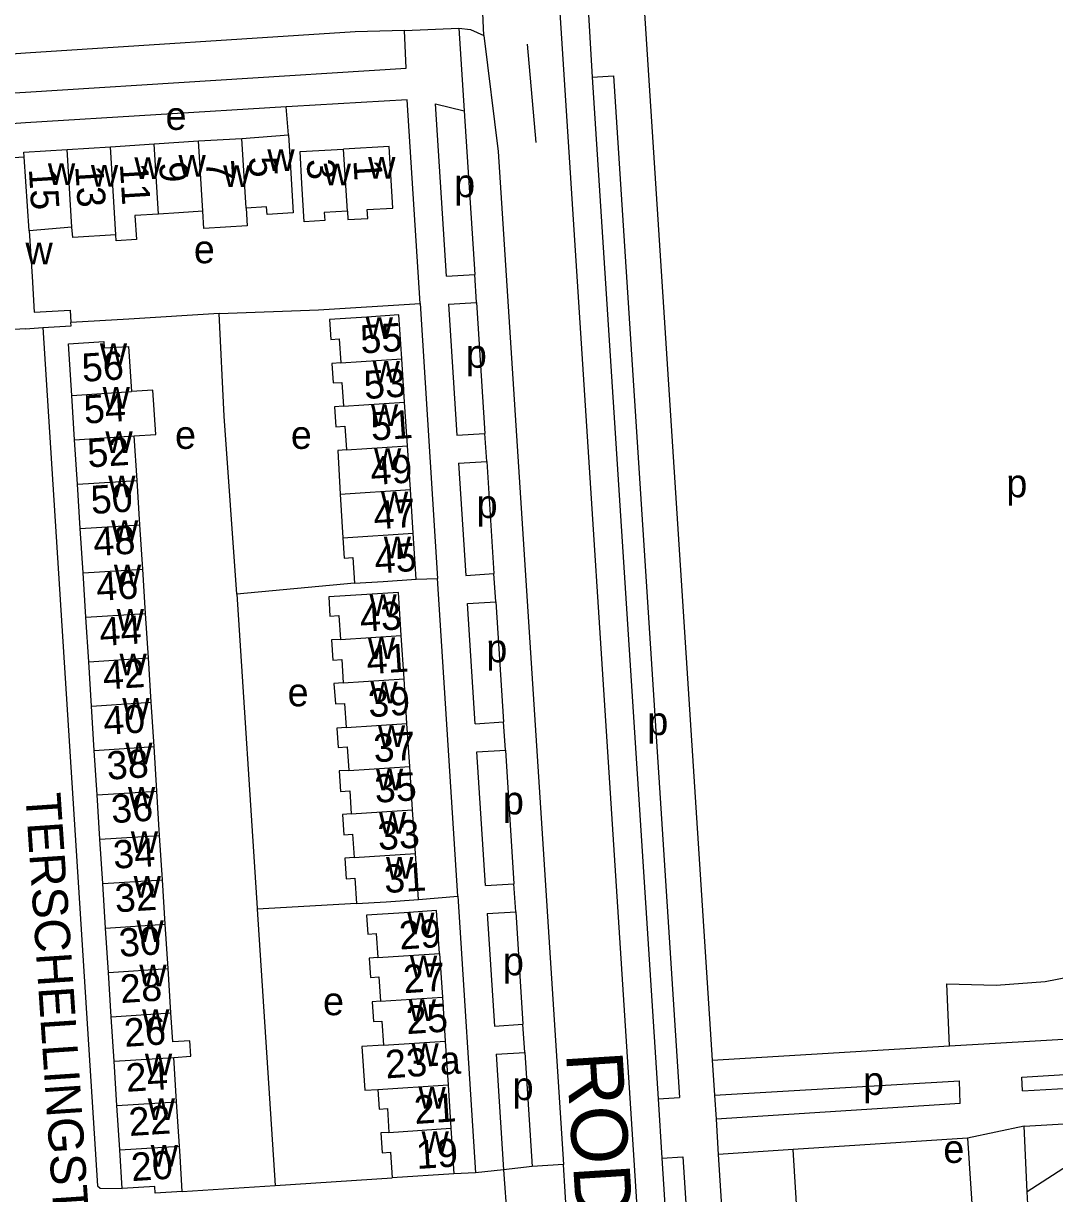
# Model space of a CAD drawing. Extents: x 159675 to 162108, y 386471 to 388472.
# Drawn here: x 160699.7 to 160845.9, y 387620 to 387785.9 of the extents above; entities that cross this region are included whole.
import ezdxf

# ---------------------------------------------------------------- set-up
doc = ezdxf.new("R2010")
doc.units = 0
for name, color, linetype in [('BLT_Basislijn', 7, 'Continuous'), ('BLT_Bebouwing', 7, 'Continuous'), ('BLT_Centroide', 7, 'Continuous'), ('BLT_Huisnummer', 7, 'Continuous'), ('BLT_Huisnummer_ tussenligend', 7, 'Continuous'), ('BLT_Huisnummer_reeks', 7, 'Continuous'), ('BLT_Onderverdeling_panden', 7, 'Continuous'), ('BLT_Straatnaam', 7, 'Continuous'), ('BLT_Straatnaam_hoofdweg', 7, 'Continuous'), ('BLT_Vlakafsluiter', 7, 'Continuous')]:
    doc.layers.add(name, color=color, linetype=linetype)

msp = doc.modelspace()

# ---------------------------------------------------------------- linework, layer by layer
at = {"layer": 'BLT_Basislijn'}
for p, q in [((160778.75, 387804.53), (160780.32, 387778.26)), ((160753.7, 387784.9), (160761.41, 387785.23)), ((160700, 387781.66), (160690.21, 387781.03)), ((160772.37, 387768.98), (160771.16, 387782.95)), ((160690.53, 387775.57), (160700, 387776.16)), ((160736.95, 387774.06), (160700, 387771.78)), ((160737.26, 387770.11), (160736.95, 387774.06)), ((160700, 387771.78), (160690.89, 387771.21)), ((160759.68, 387750.06), (160763.66, 387750.3)), ((160763.92, 387746.31), (160763.66, 387750.3)), ((160755.92, 387746.19), (160758.41, 387707.16)), ((160759.94, 387746.06), (160763.92, 387746.31)), ((160759.94, 387746.06), (160761.12, 387727.52)), ((160761.12, 387727.52), (160765.11, 387727.76)), ((160765.37, 387723.77), (160765.11, 387727.76)), ((160761.38, 387723.52), (160765.37, 387723.77)), ((160761.38, 387723.52), (160762.39, 387707.62)), ((160755.37, 387707.09), (160758.41, 387707.16)), ((160761.28, 387662.12), (160758.41, 387707.16)), ((160762.39, 387707.62), (160766.4, 387707.87)), ((160766.65, 387703.87), (160766.4, 387707.87)), ((160746.62, 387706.51), (160729.92, 387704.94)), ((160762.64, 387703.63), (160766.65, 387703.87)), ((160763.73, 387686.59), (160762.64, 387703.63)), ((160763.73, 387686.59), (160767.75, 387686.84)), ((160768.01, 387682.85), (160767.75, 387686.84)), ((160763.98, 387682.6), (160768.01, 387682.85)), ((160765.19, 387663.66), (160763.98, 387682.6)), ((160765.19, 387663.66), (160769.23, 387663.91)), ((160769.49, 387659.92), (160769.23, 387663.91)), ((160746.93, 387661.08), (160732.83, 387660.28)), ((160755.7, 387661.65), (160761.28, 387662.12)), ((160761.28, 387662.12), (160763.78, 387622.92)), ((160732.83, 387660.28), (160735.39, 387621.14)), ((160765.44, 387659.67), (160769.49, 387659.92)), ((160765.44, 387659.67), (160766.46, 387643.73)), ((160766.46, 387643.73), (160770.5, 387643.98)), ((160770.76, 387639.98), (160770.5, 387643.98)), ((160830.99, 387640.9), (160894.52, 387644.67)), ((160797.35, 387638.91), (160830.99, 387640.9)), ((160766.72, 387639.74), (160770.76, 387639.98)), ((160766.72, 387639.74), (160767.76, 387623.36)), ((160797.35, 387638.91), (160797.67, 387633.92)), ((160841.25, 387636.5), (160894.17, 387639.64)), ((160841.34, 387634.53), (160894.36, 387637.53)), ((160797.67, 387633.92), (160832.41, 387635.98)), ((160832.5, 387632.75), (160832.41, 387635.98)), ((160841.34, 387634.53), (160841.25, 387636.5)), ((160789.69, 387633.4), (160792.68, 387633.59)), ((160789.69, 387633.4), (160790.19, 387625)), ((160832.5, 387632.75), (160797.89, 387630.5)), ((160841.56, 387629.54), (160894.81, 387632.55)), ((160797.89, 387630.5), (160798.18, 387625.51)), ((160841.99, 387620.2), (160841.56, 387629.54)), ((160833.52, 387627.82), (160808.8, 387626.2)), ((160808.8, 387626.2), (160798.18, 387625.51)), ((160810.86, 387594.16), (160808.8, 387626.2)), ((160776.26, 387624.09), (160771.79, 387623.8)), ((160790.19, 387625), (160793.19, 387625.19)), ((160763.78, 387622.92), (160760.72, 387622.78)), ((160767.76, 387623.36), (160763.78, 387622.92)), ((160771.79, 387623.8), (160767.76, 387623.36)), ((160767.76, 387623.36), (160768.3, 387615.47)), ((160722.2, 387620.28), (160735.39, 387621.14)), ((160735.39, 387621.14), (160751.97, 387622.21)), ((160842.06, 387618.54), (160841.99, 387620.2))]:
    msp.add_line(p, q, dxfattribs=at)
for points in [[(160787.42, 387792.49), (160797.35, 387638.91)], [(160775.48, 387791.13), (160786.24, 387624.73)], [(160761.41, 387785.23), (160763.09, 387785.01), (160764.94, 387784.16)], [(160761.41, 387785.23), (160762.18, 387773.48)], [(160753.7, 387784.9), (160746.72, 387784.69), (160700, 387781.66)], [(160700, 387776.16), (160753.95, 387779.53), (160753.7, 387784.9)], [(160764.94, 387784.16), (160766.97, 387767.73), (160776.26, 387624.09)], [(160780.32, 387778.26), (160783.32, 387778.45), (160792.68, 387633.59)], [(160780.32, 387778.26), (160789.69, 387633.4)], [(160755.92, 387746.19), (160754.07, 387775.07), (160737.78, 387774.11), (160736.95, 387774.06)], [(160759.68, 387750.06), (160758.12, 387774.48), (160762.18, 387773.48)], [(160762.18, 387773.48), (160763.66, 387750.3)], [(160727.45, 387744.74), (160741.54, 387745.28), (160755.92, 387746.19)], [(160763.92, 387746.31), (160765.11, 387727.76)], [(160727.45, 387744.74), (160714.65, 387743.97), (160706.41, 387743.48)], [(160729.92, 387704.94), (160728.16, 387730.2), (160727.45, 387744.74)], [(160702.42, 387742.75), (160710.18, 387621.05), (160710.59, 387620.75), (160713.69, 387620.69)], [(160765.37, 387723.77), (160766.4, 387707.87)], [(160729.92, 387704.94), (160732.83, 387660.43), (160732.83, 387660.28)], [(160766.65, 387703.87), (160767.75, 387686.84)], [(160768.01, 387682.85), (160769.23, 387663.91)], [(160830.99, 387640.9), (160830.6, 387649.72), (160837.58, 387649.53), (160844.53, 387650.06), (160855.2, 387652.14), (160863.33, 387655.3), (160870.62, 387660.08), (160876.76, 387666.27), (160879.05, 387669.54), (160881.63, 387671.69), (160884, 387672.5), (160893.42, 387673.82)], [(160769.49, 387659.92), (160770.5, 387643.98)], [(160770.76, 387639.98), (160771.79, 387623.8)], [(160797.67, 387633.92), (160797.89, 387630.5)], [(160833.52, 387627.82), (160835.36, 387600.01), (160829.91, 387599.85), (160830.16, 387595.97)], [(160888.18, 387627.36), (160848.52, 387624.44), (160841.99, 387620.2)], [(160786.24, 387624.73), (160792.76, 387522.53), (160793.12, 387500.55)], [(160790.19, 387625), (160796.88, 387520.81)], [(160793.19, 387625.19), (160799.87, 387521), (160796.88, 387520.81)], [(160798.18, 387625.51), (160804.94, 387520.2)]]:
    msp.add_lwpolyline(points, dxfattribs=at)
at = {"layer": 'BLT_Bebouwing'}
for p, q in [((160730.67, 387769.59), (160737.26, 387770.11)), ((160705.89, 387767.99), (160712.02, 387768.4)), ((160712.02, 387768.4), (160718.24, 387768.82)), ((160718.24, 387768.82), (160724.49, 387769.24)), ((160724.49, 387769.24), (160730.67, 387769.59)), ((160693.5, 387766.58), (160699.78, 387766.99)), ((160700, 387742.6), (160702.42, 387742.75)), ((160753.73, 387732.19), (160753.33, 387738.33)), ((160706.95, 387726.85), (160706.55, 387733.15)), ((160754.14, 387726), (160753.73, 387732.19)), ((160707.35, 387720.56), (160706.95, 387726.85)), ((160715.8, 387721.1), (160715.4, 387727.39)), ((160754.54, 387719.8), (160754.14, 387726)), ((160707.75, 387714.27), (160707.35, 387720.56)), ((160716.2, 387714.8), (160715.8, 387721.1)), ((160754.95, 387713.62), (160754.54, 387719.8)), ((160708.15, 387707.97), (160707.75, 387714.27)), ((160716.6, 387708.51), (160716.2, 387714.8)), ((160755.37, 387707.09), (160754.95, 387713.62)), ((160708.55, 387701.68), (160708.15, 387707.97)), ((160717, 387702.22), (160716.6, 387708.51)), ((160717.4, 387695.92), (160717, 387702.22)), ((160708.95, 387695.39), (160708.55, 387701.68)), ((160753.65, 387692.95), (160753.24, 387699.12)), ((160709.35, 387689.09), (160708.95, 387695.39)), ((160717.8, 387689.63), (160717.4, 387695.92)), ((160754.06, 387686.63), (160753.65, 387692.95)), ((160709.74, 387682.8), (160709.35, 387689.09)), ((160718.2, 387683.34), (160717.8, 387689.63)), ((160754.46, 387680.54), (160754.06, 387686.63)), ((160710.14, 387676.51), (160709.74, 387682.8)), ((160718.6, 387677.04), (160718.2, 387683.34)), ((160754.87, 387674.37), (160754.46, 387680.54)), ((160710.54, 387670.21), (160710.14, 387676.51)), ((160719, 387670.75), (160718.6, 387677.04)), ((160755.27, 387668.19), (160754.87, 387674.37)), ((160719.4, 387664.46), (160719, 387670.75)), ((160710.94, 387663.92), (160710.54, 387670.21)), ((160755.7, 387661.65), (160755.27, 387668.19)), ((160711.34, 387657.62), (160710.94, 387663.92)), ((160719.8, 387658.16), (160719.4, 387664.46)), ((160711.74, 387651.33), (160711.34, 387657.62)), ((160720.2, 387651.87), (160719.8, 387658.16)), ((160758.67, 387654.01), (160759.08, 387647.84)), ((160712.14, 387645.04), (160711.74, 387651.33)), ((160759.08, 387647.84), (160759.49, 387641.6)), ((160712.54, 387638.75), (160712.14, 387645.04)), ((160759.49, 387641.6), (160759.89, 387635.41)), ((160721.4, 387632.99), (160721, 387639.28)), ((160712.94, 387632.45), (160712.54, 387638.75)), ((160759.89, 387635.41), (160760.3, 387629.23)), ((160713.34, 387626.16), (160712.94, 387632.45)), ((160721.8, 387626.7), (160721.4, 387632.99)), ((160760.3, 387629.23), (160760.72, 387622.78)), ((160713.69, 387620.69), (160713.34, 387626.16)), ((160760.72, 387622.78), (160751.97, 387622.21))]:
    msp.add_line(p, q, dxfattribs=at)
for points in [[(160737.26, 387770.11), (160737.54, 387765.45), (160737.94, 387759.02), (160734.24, 387758.79), (160734.17, 387759.86), (160731.28, 387759.68)], [(160745.61, 387759.28), (160745.67, 387758.1), (160748.5, 387758.25), (160748.43, 387759.48), (160752.04, 387759.68), (160751.56, 387768.42), (160745.07, 387768.05)], [(160699.78, 387766.99), (160699.74, 387767.61), (160705.89, 387767.99)], [(160745.61, 387759.28), (160742.33, 387759.1), (160742.4, 387757.93), (160739.49, 387757.76), (160739.17, 387763.17), (160738.9, 387767.71), (160745.07, 387768.05)], [(160700, 387742.6), (160695.02, 387742.3), (160694.55, 387750), (160693.5, 387766.58)], [(160718.86, 387758.84), (160715.5, 387758.64), (160715.71, 387755.25), (160712.85, 387755.07), (160712.79, 387755.92)], [(160725.11, 387759.27), (160721.71, 387759.02), (160718.86, 387758.84)], [(160731.28, 387759.68), (160731.43, 387757.18), (160725.26, 387756.8), (160725.11, 387759.27)], [(160706.57, 387757), (160700.51, 387756.47)], [(160712.79, 387755.92), (160706.67, 387755.55), (160706.57, 387757)], [(160700.51, 387756.47), (160700.91, 387750), (160701.22, 387744.94), (160706.3, 387745.25), (160706.41, 387743.48)], [(160702.42, 387742.75), (160706.44, 387743), (160706.41, 387743.48)], [(160753.33, 387738.33), (160752.92, 387744.55), (160748.36, 387744.25), (160743.1, 387743.91), (160743.29, 387741.07), (160744.46, 387741.15), (160744.68, 387737.76)], [(160706.55, 387733.15), (160706.08, 387740.47), (160711.07, 387740.79), (160711.13, 387739.87), (160714.6, 387740.09), (160715, 387733.68)], [(160744.68, 387737.76), (160743.42, 387737.68), (160743.6, 387734.91), (160744.83, 387734.99), (160745.05, 387731.62)], [(160715.4, 387727.39), (160718.44, 387727.58), (160718.04, 387733.88), (160715, 387733.68)], [(160745.05, 387731.62), (160743.78, 387731.54), (160743.96, 387728.7), (160745.25, 387728.79), (160745.47, 387725.43)], [(160745.47, 387725.43), (160744.24, 387725.35), (160744.61, 387719.14)], [(160744.61, 387719.14), (160744.96, 387712.97)], [(160744.96, 387712.97), (160745.15, 387710.07), (160746.38, 387710.15), (160746.62, 387706.51)], [(160746.62, 387706.51), (160750.71, 387706.78), (160755.37, 387707.09)], [(160753.24, 387699.12), (160752.85, 387705.21), (160748.38, 387704.91), (160742.97, 387704.56), (160743.14, 387701.85), (160744.41, 387701.93), (160744.64, 387698.55)], [(160744.64, 387698.55), (160743.36, 387698.47), (160743.55, 387695.6), (160744.82, 387695.68), (160745.03, 387692.39)], [(160745.03, 387692.39), (160743.71, 387692.3), (160743.91, 387689.39), (160745.2, 387689.47), (160745.42, 387686.06)], [(160745.42, 387686.06), (160744.13, 387685.97), (160744.31, 387683.23), (160745.59, 387683.32), (160745.81, 387679.97)], [(160745.81, 387679.97), (160744.47, 387679.89), (160744.66, 387677), (160745.95, 387677.08), (160746.17, 387673.8)], [(160746.17, 387673.8), (160744.91, 387673.72), (160745.1, 387670.86), (160746.34, 387670.94), (160746.56, 387667.61)], [(160746.56, 387667.61), (160745.26, 387667.53), (160745.45, 387664.62), (160746.69, 387664.7), (160746.93, 387661.08)], [(160746.93, 387661.08), (160751.13, 387661.35), (160755.7, 387661.65)], [(160758.67, 387654.01), (160758.27, 387660.09), (160753.68, 387659.79), (160748.33, 387659.44), (160748.5, 387656.76), (160749.71, 387656.84), (160749.93, 387653.44)], [(160749.93, 387653.44), (160748.71, 387653.36), (160748.89, 387650.6), (160750.08, 387650.68), (160750.31, 387647.26)], [(160720.6, 387645.58), (160720.2, 387651.87)], [(160750.31, 387647.26), (160749.12, 387647.18), (160749.31, 387644.35), (160750.52, 387644.43), (160750.75, 387641.02)], [(160721, 387639.28), (160723.44, 387639.44), (160723.3, 387641.63), (160720.86, 387641.48), (160720.6, 387645.58)], [(160750.75, 387641.02), (160747.66, 387640.82), (160748.07, 387634.63), (160749.92, 387634.75)], [(160749.92, 387634.75), (160750.1, 387631.96), (160751.28, 387632.03), (160751.5, 387628.65)], [(160751.5, 387628.65), (160750.35, 387628.58), (160750.54, 387625.75), (160751.73, 387625.83), (160751.97, 387622.21)], [(160722.2, 387620.28), (160721.89, 387625.27), (160721.8, 387626.7)], [(160722.2, 387620.28), (160718.37, 387620.04), (160718.31, 387620.98), (160713.69, 387620.69)]]:
    msp.add_lwpolyline(points, dxfattribs=at)
at = {"layer": 'BLT_Onderverdeling_panden'}
for p, q in [((160712.79, 387755.92), (160712.02, 387768.4)), ((160718.86, 387758.84), (160718.24, 387768.82)), ((160725.11, 387759.27), (160724.49, 387769.24)), ((160731.28, 387759.68), (160730.67, 387769.59)), ((160700.51, 387756.47), (160699.78, 387766.99)), ((160706.57, 387757), (160705.89, 387767.99)), ((160745.61, 387759.28), (160745.07, 387768.05)), ((160744.68, 387737.76), (160753.33, 387738.33)), ((160706.55, 387733.15), (160715, 387733.68)), ((160745.05, 387731.62), (160753.73, 387732.19)), ((160706.95, 387726.85), (160715.4, 387727.39)), ((160745.47, 387725.43), (160754.14, 387726)), ((160707.35, 387720.56), (160715.8, 387721.1)), ((160744.61, 387719.14), (160754.54, 387719.8)), ((160707.75, 387714.27), (160716.2, 387714.8)), ((160744.96, 387712.97), (160754.95, 387713.62)), ((160708.15, 387707.97), (160716.6, 387708.51)), ((160708.55, 387701.68), (160717, 387702.22)), ((160744.64, 387698.55), (160753.24, 387699.12)), ((160708.95, 387695.39), (160717.4, 387695.92)), ((160745.03, 387692.39), (160753.65, 387692.95)), ((160709.35, 387689.09), (160717.8, 387689.63)), ((160745.42, 387686.06), (160754.06, 387686.63)), ((160709.74, 387682.8), (160718.2, 387683.34)), ((160745.81, 387679.97), (160754.46, 387680.54)), ((160710.14, 387676.51), (160718.6, 387677.04)), ((160746.17, 387673.8), (160754.87, 387674.37)), ((160710.54, 387670.21), (160719, 387670.75)), ((160746.56, 387667.61), (160755.27, 387668.19)), ((160710.94, 387663.92), (160719.4, 387664.46)), ((160711.34, 387657.62), (160719.8, 387658.16)), ((160749.93, 387653.44), (160758.67, 387654.01)), ((160711.74, 387651.33), (160720.2, 387651.87)), ((160750.31, 387647.26), (160759.08, 387647.84)), ((160712.14, 387645.04), (160720.6, 387645.58)), ((160750.75, 387641.02), (160759.49, 387641.6)), ((160712.54, 387638.75), (160721, 387639.28)), ((160749.92, 387634.75), (160759.89, 387635.41)), ((160712.94, 387632.45), (160721.4, 387632.99)), ((160751.5, 387628.65), (160760.3, 387629.23)), ((160713.34, 387626.16), (160721.8, 387626.7))]:
    msp.add_line(p, q, dxfattribs=at)
at = {"layer": 'BLT_Vlakafsluiter'}
for p, q in [((160764.94, 387784.16), (160764.1, 387804.68)), ((160841.56, 387629.54), (160833.52, 387627.82)), ((160776.74, 387616.33), (160776.26, 387624.09))]:
    msp.add_line(p, q, dxfattribs=at)

# ---------------------------------------------------------------- texts
at = {"layer": 'BLT_Centroide'}
for s, p in [('e', (160719.84, 387770.79)), ('w', (160715.42, 387763.83)), ('w', (160721.67, 387764.14)), ('w', (160734.27, 387764.95)), ('w', (160748.56, 387763.86)), ('w', (160703.16, 387762.97)), ('w', (160709.25, 387762.73)), ('w', (160728, 387762.7)), ('w', (160742.25, 387762.91)), ('p', (160760.75, 387761.25)), ('w', (160699.98, 387751.72)), ('e', (160723.85, 387751.88)), ('w', (160748.21, 387741.16)), ('w', (160710.52, 387737.47)), ('p', (160762.41, 387737.06)), ('w', (160749.19, 387734.97)), ('w', (160710.91, 387731.28)), ('w', (160748.95, 387728.81)), ('e', (160721.18, 387725.56)), ('e', (160737.6, 387725.56)), ('w', (160711.31, 387724.97)), ('w', (160749.39, 387722.59)), ('w', (160711.71, 387718.69)), ('p', (160839.03, 387718.7)), ('w', (160750.37, 387716.44)), ('p', (160763.93, 387715.76)), ('w', (160712.11, 387712.38)), ('w', (160750.77, 387710.06)), ('w', (160712.51, 387706.06)), ('w', (160748.74, 387701.88)), ('w', (160712.91, 387699.78)), ('w', (160748.51, 387695.75)), ('p', (160765.31, 387695.3)), ('w', (160713.31, 387693.47)), ('e', (160737.14, 387689.06)), ('w', (160748.88, 387689.5)), ('w', (160713.71, 387687.16)), ('p', (160788.13, 387684.98)), ('w', (160749.94, 387683.31)), ('w', (160714.12, 387680.84)), ('w', (160749.66, 387677.16)), ('w', (160714.51, 387674.56)), ('p', (160767.66, 387673.73)), ('w', (160750.09, 387671)), ('w', (160714.91, 387668.25)), ('w', (160751.1, 387664.62)), ('w', (160715.31, 387661.94)), ('w', (160754.1, 387656.75)), ('w', (160715.71, 387655.62)), ('p', (160767.66, 387650.92)), ('w', (160716.12, 387649.34)), ('w', (160754.48, 387650.62)), ('e', (160742.16, 387645.26)), ('w', (160754.3, 387644.44)), ('w', (160716.52, 387643.03)), ('w', (160754.7, 387638.22)), ('w', (160716.91, 387636.72)), ('p', (160769.04, 387633.22)), ('p', (160818.72, 387633.96)), ('w', (160755.7, 387632.03)), ('w', (160717.31, 387630.41)), ('w', (160756.13, 387625.72)), ('e', (160830.1, 387624.32)), ('w', (160717.73, 387623.78))]:
    msp.add_text(s, height=4, dxfattribs=at).set_placement(p)
at = {"layer": 'BLT_Huisnummer'}
for s, rotation, p in [('5', 273.533, (160731.61, 387766.92)), ('9', 273.5293, (160718.92, 387766.19)), ('1', 273.5276, (160746.46, 387766.47)), ('15', 273.5294, (160700.45, 387765.27)), ('55', 3.7639, (160747.57, 387739.07)), ('56', 3.6346, (160708.08, 387735.06)), ('51', 3.7623, (160749.04, 387726.73)), ('52', 3.635, (160708.86, 387722.92)), ('47', 3.7637, (160749.44, 387714.14)), ('48', 3.6295, (160709.71, 387710.35)), ('43', 3.7639, (160747.49, 387699.6)), ('44', 3.6304, (160710.59, 387697.6)), ('42', 3.6274, (160711.07, 387691.43)), ('39', 3.7679, (160748.68, 387687.5)), ('40', 3.6308, (160711.13, 387684.99)), ('35', 3.7631, (160749.6, 387675.37)), ('36', 3.6312, (160712.23, 387672.48)), ('31', 3.7678, (160750.94, 387662.57)), ('32', 3.6317, (160712.76, 387659.84)), ('27', 3.7634, (160753.65, 387648.37)), ('28', 3.6325, (160713.5, 387646.98)), ('24', 3.633, (160714.32, 387634.39)), ('19', 3.7589, (160755.48, 387623.45)), ('20', 3.6273, (160715.06, 387621.73))]:
    msp.add_text(s, height=4, rotation=rotation, dxfattribs=at).set_placement(p)
at = {"layer": 'BLT_Huisnummer_ tussenligend'}
for s, rotation, p in [('13', 273.5294, (160707.03, 387765.63)), ('11', 273.5282, (160713.35, 387765.97)), ('7', 273.5272, (160725.54, 387766.42)), ('3', 273.5377, (160739.83, 387766.59)), ('53', 3.7623, (160748.08, 387732.61)), ('54', 3.635, (160708.37, 387729.13)), ('49', 3.7637, (160749, 387720.42)), ('50', 3.6291, (160709.35, 387716.32)), ('45', 3.7639, (160749.58, 387707.88)), ('46', 3.63, (160710.13, 387703.99)), ('41', 3.7679, (160748.45, 387693.61)), ('37', 3.7631, (160749.44, 387681.11)), ('38', 3.6312, (160711.61, 387678.64)), ('33', 3.7678, (160750.04, 387668.65)), ('34', 3.6317, (160712.52, 387666.02)), ('29', 3.7634, (160753.07, 387654.56)), ('30', 3.6321, (160713.34, 387653.53)), ('25', 3.7637, (160754.04, 387642.57)), ('26', 3.633, (160714.06, 387640.77)), ('21', 3.7589, (160755.2, 387629.83)), ('22', 3.6273, (160714.74, 387628.13))]:
    msp.add_text(s, height=4, rotation=rotation, dxfattribs=at).set_placement(p)
at = {"layer": 'BLT_Huisnummer_reeks'}
msp.add_text('23-a', height=4, rotation=3.7637, dxfattribs=at).set_placement((160751.1, 387636.29))
at = {"layer": 'BLT_Straatnaam'}
msp.add_text('TERSCHELLINGSTRAAT', height=5, rotation=273.8499, dxfattribs=at).set_placement((160699.95, 387676.62))
at = {"layer": 'BLT_Straatnaam_hoofdweg'}
msp.add_text('RODE KRUISLAAN', height=8, rotation=273.6049, dxfattribs=at).set_placement((160776.61, 387639.9))

doc.saveas('drawing.dxf')
